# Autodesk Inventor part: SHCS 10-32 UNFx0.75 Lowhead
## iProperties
Title: SHCS 10-32 UNFx0.75 Lowhead
Author: Neil Munro
Shininess: 48.0
PropertySet Name: _Private Model Information
Created: 2001-02
Part Number: SHCS 10-32 UNFx0.75 Lowhead
Material: Steel, Mild
Document SubType Name: Modeling
Designer: Administrator
Control State: 0
Master: False
Checked Out: False
PropertySet Name: Design Tracking Control
Density: 7.86
Volumn: 0.4698874259452923
Area: 5.082331744338173
PropertySet Name: Model Information
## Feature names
1. Body [Extrusion]
2. Head [Extrusion]
3. Hex [Extrusion]
4. Chamfer1
